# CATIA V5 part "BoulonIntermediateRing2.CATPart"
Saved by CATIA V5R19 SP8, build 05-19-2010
Part number: BoulonIntermediateRing2
Bounding box of the stored display mesh (mm): x -8 to 8, y 402 to 418, z 591 to 645
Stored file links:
  G:\EU_thinkMotion\CFAO_2010\MMS_groupe3\MMS_groupe3\A reprendre\fovide\fovide\BoulonIntermediateRing2.CATPart
  C:\Users\Rodger\Desktop\Part11.CATPart
  G:\EU_thinkMotion\CFAO_2010\MMS_groupe3\MMS_groupe3\A reprendre\fovide\fovide\fovide.CATProduct
  G:\EU_thinkMotion\CFAO_2010\MMS_groupe3\MMS_groupe3\A reprendre\fovide\fovide\Intermediate Ring 7.CATPart
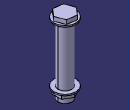
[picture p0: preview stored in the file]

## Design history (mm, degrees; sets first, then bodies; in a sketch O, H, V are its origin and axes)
Parameters
  Diametre = 10 mm
  Longueur = 42 mm
Set1
  DatumSurface1: linked copy from another document
  Point1: linked copy from another document
Body1 (main body)
Body2
  Sketch1 on DatumSurface1, origin (0, 0, 641), H (1, 0, 0), V (0, 1, 0)
    circle A1 centre (0, 410) radius 8
    point P1 (0, 410)
    reference projected point E1 (0, 410) from Point1
    radius A1 = 8 {= Diametre *8/10}
    coincidence: P1 E1
  Pad1: profile Sketch1, direction (0, 0, 1), length 1
  Sketch2 on end face of Pad1, origin (0, 0, 642), H (1, 0, 0), V (0, 1, 0)
    point P1 (0, 410)
    point P2 (2.4939, 403.4593)
    point P3 (6.9113, 408.8894)
    point P4 (4.4175, 415.4301)
    point P5 (-2.4939, 416.5407)
    point P6 (-6.9113, 411.1106)
    point P7 (-4.4175, 404.5699)
    point P8 (4.7026, 406.1744)
    line L1 (2.4939, 403.4593) -> (6.9113, 408.8894)
    line L2 (6.9113, 408.8894) -> (4.4175, 415.4301)
    line L3 (4.4175, 415.4301) -> (-2.4939, 416.5407)
    line L4 (-2.4939, 416.5407) -> (-6.9113, 411.1106)
    line L5 (-6.9113, 411.1106) -> (-4.4175, 404.5699)
    line L6 (-4.4175, 404.5699) -> (2.4939, 403.4593)
    construction line L7 (0, 410) -> (4.7026, 406.1744)
    construction circle A1 centre (0, 410) radius 7
    construction arc A2 centre (-6.9113, 411.1106) radius 7 from (-2.4939, 416.5407) to (-4.4175, 404.5699) cw
    construction arc A3 centre (6.9113, 408.8894) radius 7 from (4.4175, 415.4301) to (2.4939, 403.4593) ccw
    reference projected point E1 (0, 410) from Point1
    radius A1 = 7 {= Diametre *7/10}
    coincidence: A1 P2, A1 P3, A1 P4, A1 P5, A1 P6, A1 P7, A2 P1, A3 P1, P1 E1
    midpoint: P8 L1
    parallelism: L1 L4
  Pad2: profile Sketch2, direction (0, 0, 1), length 3
  Sketch3 on start face of Pad1, origin (0, 0, 641), H (1, 0, 0), V (0, -1, 0)
    circle A1 centre (0, -410) radius 5
    point P1 (0, -410)
    reference projected point E1 (0, -410) from Point1
    radius A1 = 5 {= Diametre /2}
    coincidence: P1 E1
  Pad3: profile Sketch3, direction (0, 0, -1), length 42 {= Longueur}
  Sketch4 on end face of Pad3, origin (0, 0, 599), H (1, 0, 0), V (0, -1, 0)
    circle A1 centre (0, -410) radius 8
    point P1 (0, -410)
    reference projected point E1 (0, -410) from Point1
    radius A1 = 8 {= Diametre *8/10}
    coincidence: P1 E1
  Pad4: profile Sketch4, direction (0, 0, -1), length 1
  Sketch5 on end face of Pad4, origin (0, 0, 598), H (1, 0, 0), V (0, -1, 0)
    point P1 (0, -410)
    point P2 (-0.0478, -416.9998)
    point P3 (6.0381, -413.5413)
    point P4 (6.0859, -406.5415)
    point P5 (0.0478, -403.0002)
    point P6 (-6.0381, -406.4587)
    point P7 (-6.0859, -413.4585)
    point P8 (2.9952, -415.2706)
    line L1 (-0.0478, -416.9998) -> (6.0381, -413.5413)
    line L2 (6.0381, -413.5413) -> (6.0859, -406.5415)
    line L3 (6.0859, -406.5415) -> (0.0478, -403.0002)
    line L4 (0.0478, -403.0002) -> (-6.0381, -406.4587)
    line L5 (-6.0381, -406.4587) -> (-6.0859, -413.4585)
    line L6 (-6.0859, -413.4585) -> (-0.0478, -416.9998)
    construction line L7 (0, -410) -> (2.9952, -415.2706)
    construction circle A1 centre (0, -410) radius 7
    construction arc A2 centre (-6.0381, -406.4587) radius 7 from (0.0478, -403.0002) to (-6.0859, -413.4585) cw
    construction arc A3 centre (6.0381, -413.5413) radius 7 from (6.0859, -406.5415) to (-0.0478, -416.9998) ccw
    reference projected point E1 (0, -410) from Point1
    radius A1 = 7 {= Diametre *7/10}
    coincidence: A1 P2, A1 P3, A1 P4, A1 P5, A1 P6, A1 P7, A2 P1, A3 P1, P1 E1
    midpoint: P8 L1
    parallelism: L1 L4
  Pad5: profile Sketch5, direction (0, 0, -1), length 3
  Sketch6 on end face of Pad5, origin (0, 0, 595), H (1, 0, 0), V (0, -1, 0)
    circle A1 centre (0, -410) radius 5
    point P1 (0, -410)
    reference projected point E1 (0, -410) from Point1
    radius A1 = 5 {= Diametre /2}
    coincidence: P1 E1
  Pad6: profile Sketch6, direction (0, 0, -1), length 4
